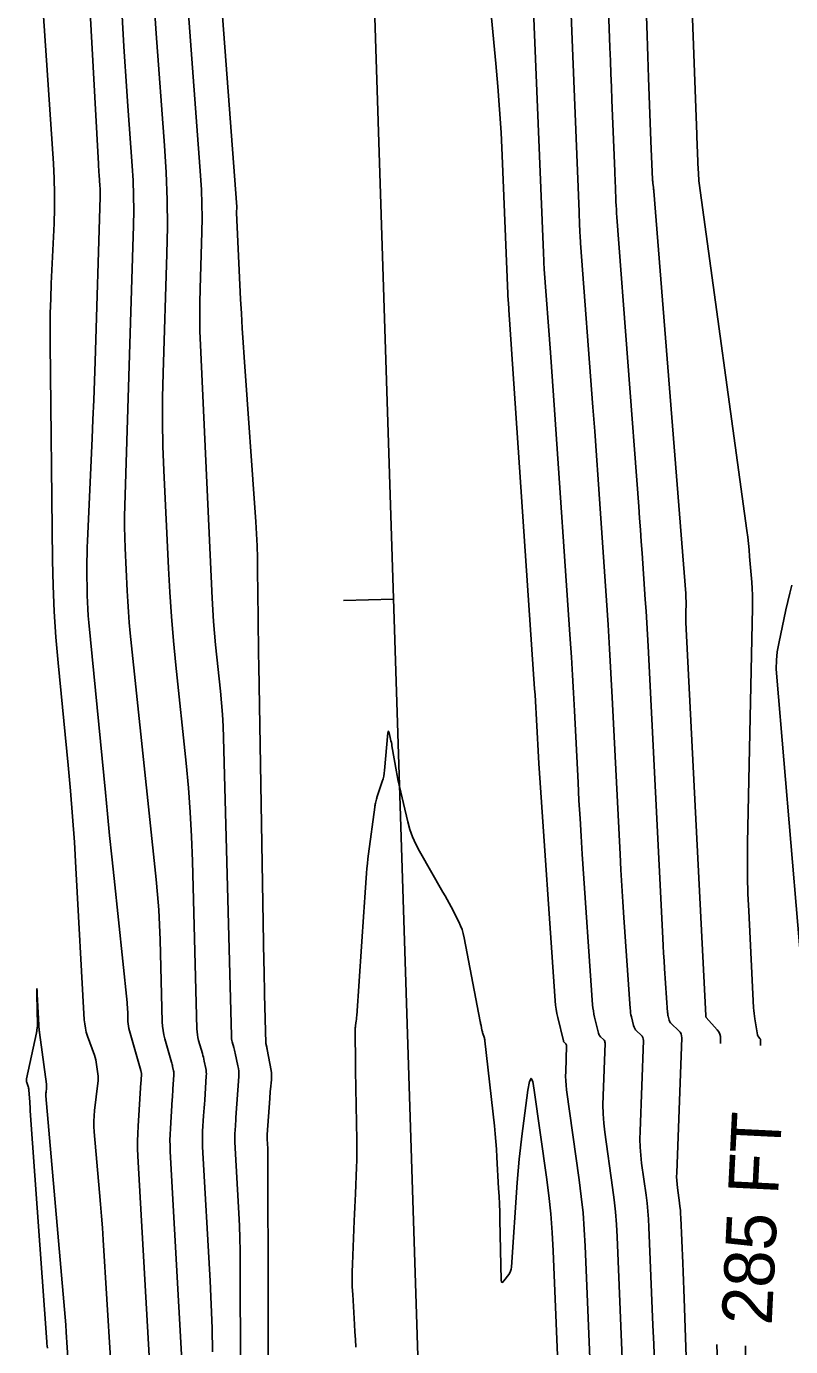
# Model space of a CAD drawing. Extents: x 1768942 to 1774819, y 723037 to 732099.
# Drawn here: x 1770770.3 to 1770861.8, y 724947.7 to 725105.6 of the extents above; entities that cross this region are included whole.
import ezdxf

# ---------------------------------------------------------------- set-up
doc = ezdxf.new("R2010")
doc.units = 0
for name, color, linetype in [('R_Contour Annot', 7, 'Continuous'), ('R_Contours', 7, 'Continuous'), ('R_Horz Alg', 7, 'Continuous')]:
    doc.layers.add(name, color=color, linetype=linetype)

msp = doc.modelspace()

# ---------------------------------------------------------------- linework, layer by layer
at = {"layer": 'R_Contours'}
for points in [[(1770853.39, 724983.92), (1770853.41, 724984.43), (1770853.39, 724984.75), (1770853.32, 724985.05), (1770853.18, 724985.32), (1770852.99, 724985.58), (1770851.69, 724987.03), (1770851.67, 724987.04), (1770851.66, 724987.06), (1770851.66, 724987.08), (1770851.65, 724987.1), (1770851.64, 724987.19), (1770851.63, 724987.22), (1770851.63, 724987.24), (1770851.63, 724987.26), (1770851.63, 724987.28), (1770849.26, 725034.31), (1770849.25, 725034.6), (1770849.24, 725034.89), (1770849.24, 725035.18), (1770849.24, 725035.47), (1770849.27, 725036.62), (1770849.27, 725036.9), (1770849.26, 725037.19), (1770849.25, 725037.48), (1770849.23, 725037.77), (1770845.42, 725085.92), (1770845.41, 725086.04), (1770845.39, 725086.16), (1770845.38, 725086.27), (1770845.37, 725086.39), (1770845.3, 725086.85), (1770845.29, 725086.97), (1770845.28, 725087.08), (1770845.27, 725087.2), (1770845.26, 725087.32), (1770845.06, 725091.93), (1770845.06, 725091.96), (1770844.79, 725099.51), (1770844.74, 725100.77), (1770844.7, 725102.03), (1770844.65, 725103.29), (1770844.61, 725104.55), (1770843.32, 725141.53)], [(1770839.08, 725133.61), (1770840.15, 725103.11), (1770840.21, 725101.54), (1770840.27, 725099.97), (1770840.33, 725098.4), (1770840.39, 725096.83), (1770840.73, 725088.33), (1770840.75, 725087.87), (1770840.77, 725087.41), (1770840.79, 725086.95), (1770840.81, 725086.49), (1770840.88, 725084.66), (1770840.9, 725084.2), (1770840.93, 725083.74), (1770840.96, 725083.28), (1770840.99, 725082.82), (1770843.61, 725048.19), (1770843.71, 725046.8), (1770843.82, 725045.41), (1770843.91, 725044.01), (1770844.01, 725042.62), (1770844.39, 725037.05), (1770844.48, 725035.66), (1770844.57, 725034.27), (1770844.65, 725032.87), (1770844.72, 725031.48), (1770846.48, 724996.55), (1770846.53, 724995.63), (1770846.58, 724994.72), (1770846.63, 724993.8), (1770846.7, 724992.89), (1770847.06, 724987.64), (1770847.07, 724987.52), (1770847.08, 724987.41), (1770847.1, 724987.29), (1770847.13, 724987.18), (1770847.24, 724986.71), (1770847.28, 724986.6), (1770847.33, 724986.5), (1770847.39, 724986.41), (1770847.47, 724986.32), (1770848.4, 724985.46), (1770848.56, 724985.28), (1770848.67, 724985.08), (1770848.74, 724984.86), (1770848.75, 724984.62), (1770848.15, 724968.43), (1770848.14, 724967.98), (1770848.15, 724967.53), (1770848.19, 724967.09), (1770848.24, 724966.64), (1770848.49, 724964.87), (1770848.54, 724964.42), (1770848.59, 724963.98), (1770848.62, 724963.53), (1770848.65, 724963.08), (1770848.87, 724957.64), (1770848.91, 724956.58), (1770848.95, 724955.53), (1770848.99, 724954.47), (1770849.03, 724953.41), (1770850.05, 724924.26)], [(1770789.1, 724943.12), (1770787.54, 724971), (1770787.51, 724971.68), (1770787.5, 724972.37), (1770787.51, 724973.05), (1770787.55, 724973.74), (1770787.78, 724977.21), (1770787.8, 724977.52), (1770787.82, 724977.84), (1770787.84, 724978.16), (1770787.86, 724978.48), (1770787.97, 724980.12), (1770787.97, 724980.25), (1770787.97, 724980.38), (1770787.96, 724980.52), (1770787.93, 724980.65), (1770787.82, 724981.17), (1770787.79, 724981.3), (1770787.76, 724981.43), (1770787.73, 724981.56), (1770787.69, 724981.69), (1770786.9, 724984.47), (1770786.77, 724984.98), (1770786.68, 724985.49), (1770786.61, 724986.01), (1770786.58, 724986.53), (1770786.33, 724996.33), (1770786.27, 724998.13), (1770786.17, 724999.94), (1770786.03, 725001.74), (1770785.86, 725003.54), (1770782.76, 725033.03), (1770782.64, 725034.3), (1770782.53, 725035.57), (1770782.45, 725036.84), (1770782.38, 725038.11), (1770782.14, 725043.2), (1770782.1, 725044.47), (1770782.07, 725045.75), (1770782.08, 725047.02), (1770782.1, 725048.29), (1770783.14, 725081.83), (1770783.18, 725083.62), (1770783.16, 725085.41), (1770783.1, 725087.19), (1770782.99, 725088.97), (1770782.46, 725096.11), (1770782.34, 725097.89), (1770782.22, 725099.68), (1770782.11, 725101.46), (1770782, 725103.25), (1770780.4, 725132.46)], [(1770771.16, 725124.54), (1770773.55, 725089.23), (1770773.64, 725087.43), (1770773.69, 725085.64), (1770773.68, 725083.84), (1770773.63, 725082.05), (1770773.3, 725074.87), (1770773.23, 725073.07), (1770773.18, 725071.27), (1770773.17, 725069.48), (1770773.17, 725067.68), (1770773.45, 725041.77), (1770773.52, 725038.69), (1770773.65, 725035.62), (1770773.85, 725032.55), (1770774.12, 725029.48), (1770775.31, 725017.22), (1770775.6, 725014.15), (1770775.85, 725011.09), (1770776.06, 725008.01), (1770776.25, 725004.94), (1770777.25, 724986.77), (1770777.3, 724986.27), (1770777.38, 724985.78), (1770777.49, 724985.3), (1770777.64, 724984.82), (1770778.47, 724982.54), (1770778.55, 724982.26), (1770778.63, 724981.99), (1770778.69, 724981.71), (1770778.73, 724981.43), (1770778.88, 724980.29), (1770778.91, 724980.01), (1770778.92, 724979.73), (1770778.91, 724979.44), (1770778.89, 724979.16), (1770778.49, 724975.9), (1770778.43, 724975.26), (1770778.41, 724974.62), (1770778.41, 724973.98), (1770778.45, 724973.34), (1770779.09, 724966.11), (1770779.21, 724964.69), (1770779.32, 724963.27), (1770779.42, 724961.85), (1770779.51, 724960.43), (1770781.27, 724932.03)], [(1770824.86, 725118.48), (1770826.51, 725101.21), (1770826.76, 725098.46), (1770826.96, 725095.71), (1770827.13, 725092.95), (1770827.26, 725090.19), (1770827.93, 725073.66), (1770827.94, 725073.53), (1770827.94, 725073.51), (1770827.94, 725073.5), (1770827.94, 725073.48), (1770827.94, 725073.46), (1770828.02, 725072.44), (1770828.03, 725072.27), (1770828.05, 725072.09), (1770828.06, 725071.92), (1770828.07, 725071.74), (1770831.15, 725026.39), (1770831.2, 725025.64), (1770831.25, 725024.9), (1770831.29, 725024.15), (1770831.33, 725023.41), (1770831.48, 725020.43), (1770831.52, 725019.69), (1770831.56, 725018.94), (1770831.6, 725018.2), (1770831.65, 725017.45), (1770833.61, 724989.02), (1770833.66, 724988.52), (1770833.72, 724988.02), (1770833.81, 724987.53), (1770833.92, 724987.04), (1770834.6, 724984.24), (1770834.61, 724984.18), (1770834.64, 724984.13), (1770834.67, 724984.08), (1770834.72, 724984.03), (1770834.9, 724983.87), (1770834.94, 724983.82), (1770834.96, 724983.77), (1770834.98, 724983.72), (1770834.98, 724983.66), (1770834.87, 724980.55), (1770834.86, 724980.01), (1770834.87, 724979.47), (1770834.91, 724978.94), (1770834.97, 724978.4), (1770836.48, 724967.61), (1770836.73, 724965.63), (1770836.94, 724963.64), (1770837.09, 724961.66), (1770837.2, 724959.66), (1770838.46, 724929.08)], [(1770777.43, 725116.8), (1770778.94, 725089.19), (1770778.96, 725088.86), (1770778.98, 725088.53), (1770779.01, 725088.2), (1770779.03, 725087.88), (1770779.13, 725086.56), (1770779.15, 725086.23), (1770779.16, 725085.9), (1770779.16, 725085.57), (1770779.15, 725085.25), (1770778.54, 725065.55), (1770778.47, 725063.24), (1770778.38, 725060.93), (1770778.29, 725058.62), (1770778.19, 725056.32), (1770777.63, 725044.1), (1770777.6, 725043.28), (1770777.58, 725042.47), (1770777.57, 725041.65), (1770777.57, 725040.83), (1770777.61, 725037.56), (1770777.63, 725036.75), (1770777.66, 725035.93), (1770777.71, 725035.12), (1770777.78, 725034.3), (1770779.77, 725013.97), (1770780.02, 725011.4), (1770780.28, 725008.83), (1770780.54, 725006.26), (1770780.81, 725003.69), (1770782.37, 724988.84), (1770782.4, 724988.55), (1770782.42, 724988.27), (1770782.44, 724987.98), (1770782.45, 724987.7), (1770782.48, 724986.55), (1770782.49, 724986.27), (1770782.53, 724985.99), (1770782.58, 724985.71), (1770782.65, 724985.43), (1770784, 724980.68), (1770784.02, 724980.64), (1770784.03, 724980.6), (1770784.04, 724980.56), (1770784.04, 724980.52), (1770784.08, 724980.35), (1770784.09, 724980.31), (1770784.09, 724980.27), (1770784.09, 724980.23), (1770784.09, 724980.18), (1770784.06, 724979.67), (1770784.04, 724979.47), (1770784.03, 724979.27), (1770783.69, 724974.05), (1770783.64, 724973.15), (1770783.62, 724972.24), (1770783.63, 724971.34), (1770783.67, 724970.44), (1770785.96, 724929.67)], [(1770789.02, 725116.83), (1770791.16, 725087.79), (1770791.27, 725086.1), (1770791.33, 725084.41), (1770791.34, 725082.72), (1770791.31, 725081.03), (1770791.1, 725074.27), (1770791.06, 725072.57), (1770791.06, 725070.88), (1770791.09, 725069.19), (1770791.15, 725067.5), (1770792.55, 725037.24), (1770792.62, 725035.84), (1770792.72, 725034.44), (1770792.83, 725033.05), (1770792.97, 725031.65), (1770793.55, 725026.08), (1770793.69, 725024.69), (1770793.79, 725023.29), (1770793.87, 725021.89), (1770793.92, 725020.49), (1770794.85, 724984.83), (1770794.86, 724984.65), (1770794.88, 724984.47), (1770794.91, 724984.3), (1770794.95, 724984.13), (1770795.15, 724983.45), (1770795.19, 724983.28), (1770795.24, 724983.11), (1770795.28, 724982.94), (1770795.32, 724982.76), (1770795.64, 724981.24), (1770795.69, 724980.93), (1770795.73, 724980.62), (1770795.74, 724980.3), (1770795.73, 724979.99), (1770795.4, 724975.08), (1770795.39, 724974.83), (1770795.37, 724974.59), (1770795.35, 724974.34), (1770795.34, 724974.09), (1770795.27, 724973.11), (1770795.26, 724972.86), (1770795.25, 724972.61), (1770795.26, 724972.37), (1770795.27, 724972.12), (1770795.74, 724963.62), (1770795.82, 724962.12), (1770795.87, 724960.62), (1770795.91, 724959.12), (1770795.92, 724957.62), (1770795.97, 724931.71)], [(1770799.28, 724934.17), (1770799.21, 724971.03), (1770799.21, 724971.2), (1770799.2, 724971.37), (1770799.2, 724971.54), (1770799.19, 724971.71), (1770799.13, 724972.68), (1770799.13, 724972.71), (1770799.13, 724972.74), (1770799.13, 724972.76), (1770799.13, 724972.79), (1770799.15, 724972.99), (1770799.15, 724973.02), (1770799.44, 724977.36), (1770799.46, 724977.64), (1770799.48, 724977.92), (1770799.5, 724978.19), (1770799.53, 724978.47), (1770799.64, 724979.58), (1770799.66, 724979.86), (1770799.66, 724980.13), (1770799.64, 724980.41), (1770799.6, 724980.68), (1770799.14, 724983.2), (1770799.12, 724983.27), (1770799.11, 724983.35), (1770799.09, 724983.42), (1770799.08, 724983.5), (1770798.98, 724983.94), (1770798.98, 724983.95), (1770798.98, 724983.96), (1770798.98, 724983.97), (1770798.98, 724983.97), (1770798.83, 724989.77), (1770798.8, 724990.74), (1770798.78, 724991.71), (1770798.76, 724992.67), (1770798.74, 724993.64), (1770798.13, 725029.13), (1770798.1, 725030.57), (1770798.08, 725032), (1770798.07, 725033.44), (1770798.05, 725034.88), (1770798, 725040.63), (1770797.98, 725042.06), (1770797.93, 725043.5), (1770797.86, 725044.93), (1770797.77, 725046.37), (1770796.37, 725066.06), (1770796.25, 725067.8), (1770796.14, 725069.54), (1770796.05, 725071.27), (1770795.96, 725073.01), (1770795.48, 725083.33), (1770795.48, 725083.39), (1770795.48, 725083.45), (1770795.48, 725083.51), (1770795.48, 725083.57), (1770795.49, 725083.8), (1770795.49, 725083.86), (1770795.49, 725083.92), (1770795.49, 725083.98), (1770795.49, 725084.04), (1770793.05, 725117)], [(1770841.81, 724941.35), (1770841.01, 724960.8), (1770840.94, 724962.28), (1770840.82, 724963.76), (1770840.67, 724965.23), (1770840.48, 724966.69), (1770839.56, 724973.33), (1770839.43, 724974.41), (1770839.35, 724975.5), (1770839.32, 724976.58), (1770839.34, 724977.68), (1770839.57, 724983.98), (1770839.56, 724984.1), (1770839.53, 724984.21), (1770839.48, 724984.31), (1770839.4, 724984.4), (1770839.03, 724984.74), (1770838.95, 724984.83), (1770838.88, 724984.92), (1770838.83, 724985.03), (1770838.79, 724985.15), (1770838.32, 724987.09), (1770838.24, 724987.45), (1770838.18, 724987.82), (1770838.13, 724988.19), (1770838.09, 724988.56), (1770836.85, 725006.58), (1770836.71, 725008.72), (1770836.58, 725010.87), (1770836.45, 725013.01), (1770836.34, 725015.16), (1770835.91, 725023.73), (1770835.8, 725025.88), (1770835.68, 725028.02), (1770835.54, 725030.16), (1770835.4, 725032.31), (1770833.54, 725059.77), (1770833.42, 725061.48), (1770833.3, 725063.2), (1770833.17, 725064.91), (1770833.04, 725066.62), (1770832.29, 725076.58), (1770832.28, 725076.75), (1770832.27, 725076.91), (1770832.26, 725077.07), (1770832.25, 725077.24), (1770832.23, 725077.9), (1770832.21, 725078.22), (1770832.2, 725078.55), (1770830.79, 725113.41)], [(1770858.16, 724983.69), (1770858.19, 724984.31), (1770858.18, 724984.37), (1770858.17, 724984.43), (1770858.14, 724984.49), (1770858.1, 724984.54), (1770857.92, 724984.74), (1770857.88, 724984.79), (1770857.85, 724984.85), (1770857.82, 724984.91), (1770857.81, 724984.98), (1770857.49, 724986.86), (1770857.44, 724987.19), (1770857.4, 724987.53), (1770857.37, 724987.87), (1770857.35, 724988.21), (1770856.77, 724999.79), (1770856.68, 725001.83), (1770856.63, 725003.87), (1770856.62, 725005.92), (1770856.64, 725007.96), (1770857.22, 725036.05), (1770857.22, 725036.82), (1770857.21, 725037.59), (1770857.18, 725038.37), (1770857.13, 725039.14), (1770856.88, 725042.22), (1770856.81, 725042.99), (1770856.74, 725043.76), (1770856.65, 725044.53), (1770856.55, 725045.3), (1770850.84, 725086.89), (1770850.81, 725087.18), (1770850.78, 725087.48), (1770850.75, 725087.77), (1770850.74, 725088.06), (1770850.69, 725089.26), (1770850.67, 725089.55), (1770850.66, 725089.83), (1770850.65, 725090.12), (1770850.64, 725090.41), (1770850.59, 725091.56), (1770850.58, 725091.84), (1770850.57, 725092.13), (1770850.56, 725092.42), (1770850.54, 725092.7), (1770849.89, 725110.9)], [(1770785.65, 725107.8), (1770785.86, 725104.78), (1770786.86, 725091.39), (1770787.05, 725088.15), (1770787.16, 725084.91), (1770787.19, 725081.67), (1770787.13, 725078.42), (1770786.69, 725064.15), (1770786.63, 725061.23), (1770786.62, 725058.32), (1770786.67, 725055.4), (1770786.78, 725052.49), (1770787.32, 725040.83), (1770787.47, 725037.92), (1770787.67, 725035.01), (1770787.91, 725032.1), (1770788.19, 725029.2), (1770789.43, 725017.46), (1770789.71, 725014.54), (1770789.93, 725011.61), (1770790.09, 725008.68), (1770790.19, 725005.74), (1770790.72, 724985.68), (1770790.74, 724985.33), (1770790.78, 724984.98), (1770790.84, 724984.64), (1770790.93, 724984.3), (1770791.38, 724982.71), (1770791.44, 724982.49), (1770791.5, 724982.27), (1770791.55, 724982.05), (1770791.6, 724981.83), (1770791.79, 724980.95), (1770791.82, 724980.72), (1770791.85, 724980.5), (1770791.86, 724980.28), (1770791.85, 724980.05), (1770791.66, 724977.15), (1770791.62, 724976.68), (1770791.59, 724976.21), (1770791.56, 724975.75), (1770791.53, 724975.28), (1770791.41, 724973.42), (1770791.39, 724972.96), (1770791.38, 724972.49), (1770791.38, 724972.02), (1770791.4, 724971.56), (1770792.3, 724955.52), (1770792.44, 724952.69), (1770792.54, 724949.86), (1770792.61, 724947.03)], [(1770845.49, 724945.68), (1770845.4, 724947.96), (1770845.31, 724950.23), (1770844.83, 724961.94), (1770844.78, 724962.91), (1770844.7, 724963.87), (1770844.61, 724964.83), (1770844.48, 724965.78), (1770843.95, 724969.6), (1770843.84, 724970.56), (1770843.77, 724971.52), (1770843.74, 724972.48), (1770843.76, 724973.44), (1770844.16, 724984.3), (1770844.15, 724984.48), (1770844.1, 724984.64), (1770844.02, 724984.79), (1770843.9, 724984.93), (1770843.35, 724985.44), (1770843.22, 724985.57), (1770843.12, 724985.72), (1770843.04, 724985.88), (1770842.98, 724986.06), (1770842.72, 724987.13), (1770842.67, 724987.37), (1770842.63, 724987.61), (1770842.6, 724987.86), (1770842.57, 724988.1), (1770841.82, 724999), (1770841.7, 725000.89), (1770841.58, 725002.79), (1770841.47, 725004.69), (1770841.37, 725006.59), (1770840.43, 725025.35), (1770840.28, 725028.25), (1770840.11, 725031.14), (1770839.93, 725034.04), (1770839.74, 725036.93), (1770838.96, 725048.51), (1770838.76, 725051.41), (1770838.55, 725054.3), (1770838.34, 725057.19), (1770838.12, 725060.09), (1770836.64, 725079.7), (1770836.62, 725080.01), (1770836.6, 725080.32), (1770836.58, 725080.63), (1770836.57, 725080.95), (1770836.52, 725082.2), (1770836.5, 725082.51), (1770836.49, 725082.82), (1770836.48, 725083.13), (1770836.47, 725083.44), (1770835.71, 725102.08), (1770835.59, 725105.08), (1770835.48, 725108.08)], [(1770861.94, 725038.79), (1770861.67, 725037.8), (1770861.43, 725036.81), (1770861.21, 725035.81), (1770860.36, 725031.81), (1770860.19, 725030.8), (1770860.09, 725029.79), (1770860.07, 725028.78), (1770860.12, 725027.76), (1770863.5, 724988.2)], [(1770809.74, 724947.6), (1770809.69, 724948.5), (1770809.64, 724949.4), (1770809.59, 724950.3), (1770809.37, 724953.9), (1770809.32, 724954.8), (1770809.3, 724955.7), (1770809.31, 724956.6), (1770809.34, 724957.5), (1770809.56, 724962.71), (1770809.6, 724963.52), (1770809.63, 724964.32), (1770809.66, 724965.12), (1770809.7, 724965.93), (1770809.82, 724969.14), (1770809.85, 724969.94), (1770809.86, 724970.74), (1770809.87, 724971.54), (1770809.86, 724972.35), (1770809.74, 724978.57), (1770809.73, 724979.3), (1770809.72, 724980.02), (1770809.71, 724980.74), (1770809.7, 724981.46), (1770809.67, 724985.49), (1770809.67, 724985.64), (1770809.68, 724985.79), (1770809.69, 724985.93), (1770809.71, 724986.08), (1770809.79, 724986.65), (1770809.81, 724986.8), (1770809.83, 724986.94), (1770809.84, 724987.09), (1770809.85, 724987.24), (1770810.69, 724999.68), (1770810.73, 725000.25), (1770810.77, 725000.83), (1770810.82, 725001.41), (1770810.86, 725001.99), (1770811.03, 725004.31), (1770811.08, 725004.88), (1770811.13, 725005.46), (1770811.2, 725006.04), (1770811.27, 725006.61), (1770812.02, 725012.2), (1770812.03, 725012.32), (1770812.05, 725012.44), (1770812.08, 725012.56), (1770812.1, 725012.68), (1770812.22, 725013.15), (1770812.25, 725013.27), (1770812.28, 725013.38), (1770812.31, 725013.5), (1770812.35, 725013.61), (1770812.91, 725015.29), (1770813, 725015.61), (1770813.08, 725015.93), (1770813.14, 725016.26), (1770813.18, 725016.59), (1770813.59, 725021.11), (1770813.61, 725021.26), (1770813.64, 725021.32), (1770813.67, 725021.27), (1770813.72, 725021.12), (1770813.91, 725020.33), (1770813.95, 725020.13), (1770814, 725019.93), (1770814.04, 725019.73), (1770814.07, 725019.53), (1770814.6, 725016.44), (1770814.64, 725016.21), (1770814.69, 725015.98), (1770814.73, 725015.75), (1770814.78, 725015.52), (1770815.97, 725010.44), (1770816.22, 725009.53), (1770816.53, 725008.64), (1770816.91, 725007.78), (1770817.35, 725006.95), (1770820.18, 725002.05), (1770820.43, 725001.61), (1770820.67, 725001.17), (1770820.91, 725000.72), (1770821.14, 725000.28), (1770822.07, 724998.48), (1770822.29, 724998.02), (1770822.47, 724997.56), (1770822.61, 724997.08), (1770822.72, 724996.59), (1770824.63, 724986.55), (1770824.66, 724986.42), (1770824.68, 724986.3), (1770824.7, 724986.18), (1770824.73, 724986.06), (1770824.83, 724985.54), (1770824.86, 724985.43), (1770824.89, 724985.32), (1770824.92, 724985.22), (1770824.95, 724985.11), (1770825.1, 724984.69), (1770825.13, 724984.58), (1770825.16, 724984.47), (1770825.18, 724984.37), (1770825.2, 724984.26), (1770826.33, 724974.06), (1770826.43, 724973.12), (1770826.51, 724972.19), (1770826.58, 724971.26), (1770826.64, 724970.32), (1770826.84, 724966.58), (1770826.89, 724965.64), (1770826.93, 724964.7), (1770826.97, 724963.77), (1770826.99, 724962.83), (1770827.16, 724955.6), (1770827.18, 724955.41), (1770827.24, 724955.34), (1770827.33, 724955.37), (1770827.46, 724955.51), (1770828.04, 724956.28), (1770828.17, 724956.48), (1770828.27, 724956.69), (1770828.33, 724956.91), (1770828.37, 724957.15), (1770829.06, 724967.29), (1770829.16, 724968.68), (1770829.29, 724970.07), (1770829.44, 724971.45), (1770829.62, 724972.83), (1770830.35, 724978.36), (1770830.54, 724979.39), (1770830.73, 724979.74), (1770830.92, 724979.39), (1770831.11, 724978.36), (1770832.56, 724967.94), (1770832.84, 724965.74), (1770833.07, 724963.53), (1770833.24, 724961.32), (1770833.36, 724959.11), (1770835.1, 724916.8)], [(1770772.83, 724947.48), (1770772.81, 724947.73), (1770772.78, 724947.98), (1770772.76, 724948.23), (1770770.79, 724975.86), (1770770.77, 724976.13), (1770770.76, 724976.4), (1770770.74, 724976.67), (1770770.72, 724976.94), (1770770.63, 724978.33), (1770770.61, 724978.44), (1770770.59, 724978.56), (1770770.57, 724978.68), (1770770.53, 724978.79), (1770770.37, 724979.24), (1770770.34, 724979.35), (1770770.32, 724979.47), (1770770.32, 724979.58), (1770770.34, 724979.7), (1770771.54, 724985.22), (1770771.55, 724985.3), (1770771.57, 724985.37), (1770771.58, 724985.45), (1770771.59, 724985.52), (1770771.63, 724985.82), (1770771.64, 724985.9), (1770771.65, 724985.97), (1770771.65, 724986.05), (1770771.65, 724986.12), (1770771.58, 724989.84), (1770771.58, 724990.32), (1770771.58, 724990.48), (1770771.6, 724990.32), (1770771.63, 724989.84), (1770771.87, 724985.41), (1770771.87, 724985.4), (1770771.88, 724985.39), (1770771.88, 724985.37), (1770771.88, 724985.36), (1770771.9, 724985.31), (1770771.91, 724985.3), (1770771.91, 724985.29), (1770771.91, 724985.27), (1770771.91, 724985.26), (1770772.73, 724979.06), (1770772.74, 724978.94), (1770772.74, 724978.83), (1770772.74, 724978.71), (1770772.73, 724978.59), (1770772.67, 724978.12), (1770772.66, 724978), (1770772.66, 724977.89), (1770772.66, 724977.77), (1770772.66, 724977.65), (1770774.82, 724953.01), (1770774.9, 724952.1), (1770774.97, 724951.19), (1770775.04, 724950.27), (1770775.1, 724949.36), (1770775.32, 724945.71)], [(1770854.03, 724916.7), (1770852.96, 724947.9)], [(1770856.39, 724946.49), (1770856.39, 724947.73)]]:
    msp.add_lwpolyline(points, dxfattribs=at)
at = {"layer": 'R_Horz Alg'}
msp.add_line((1770821.12, 724822.68), (1770798.66, 725525.31), dxfattribs=at)
msp.add_line((1770821.12, 724822.68), (1770798.66, 725525.31), dxfattribs=at)
msp.add_lwpolyline([(1770808.27, 725036.93), (1770814.26, 725037.12)], dxfattribs=at)

# ---------------------------------------------------------------- texts
at = {"layer": 'R_Contour Annot'}
msp.add_text('285 FT', height=6, rotation=87.1785, dxfattribs=at).set_placement((1770859.51, 724950.15))

doc.saveas('drawing.dxf')
